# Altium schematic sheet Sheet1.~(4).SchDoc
size A4; SheetNumber: 1; SheetTotal: 1; SPICEModelCacheJFKDNKES: <root> / <DocumentId>JFKDNKES</DocumentId> / <CacheFrame Number="0"> / <Model Name="2n3904" Kind="MDL"> / <Text>*2N3904 / *Si 310mW  40V 200mA 300MHz pkg:TO-92B 1,2,3 / .MODEL 2N3904 NPN(IS=1.4E-14 BF=300 VAF=100 IKF=0.025 ISE=3E-13 / + BR=7.5 RC=2.4 CJE=4.5E-12 TF=4E-10 CJC=3.5E-12 TR=2.1E-8 XTB=1.5 KF=9E-16 )</Text> / </Model> / </CacheFrame> / </root>
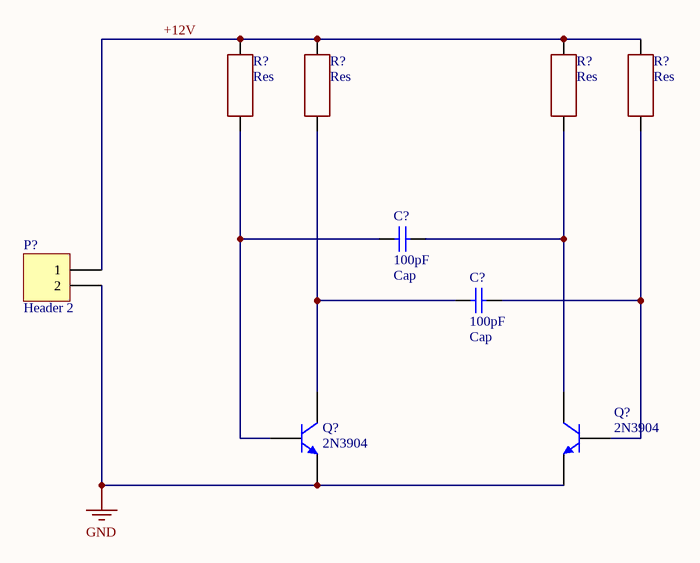
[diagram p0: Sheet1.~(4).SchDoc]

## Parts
(Parts that share a designator on the sheet are numbered #1, #2 ... from top to bottom, then left to right.)
C?#1  Cap  value 100pF  [RAD-0.3]
C?#2  Cap  value 100pF  [RAD-0.3]
P?  Header 2  [HDR1X2]
Q?#1  2N3904  [TO-92A]
Q?#2  2N3904  [TO-92A]
R?#1  Res  [Res 0805]
R?#2  Res  [Res 0805]
R?#3  Res  [Res 0805]
R?#4  Res  [Res 0805]

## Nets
GND: P?.2 Q?#1.1(E) Q?#2.1(E)
+12V: P?.1 R?#1.2 R?#2.2 R?#3.2 R?#4.2
NetC?#1_1: C?#1.1 Q?#1.2(B) R?#1.1
NetC?#1_2: C?#1.2 Q?#2.3(C) R?#3.1
NetC?#2_1: C?#2.1 Q?#1.3(C) R?#2.1
NetC?#2_2: C?#2.2 Q?#2.2(B) R?#4.1

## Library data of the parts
C?#1 C?#2 = Cap: Capacitor
P? = Header 2: Header, 2-Pin
Q?#1 Q?#2 = 2N3904: NPN General Purpose Amplifier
